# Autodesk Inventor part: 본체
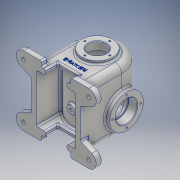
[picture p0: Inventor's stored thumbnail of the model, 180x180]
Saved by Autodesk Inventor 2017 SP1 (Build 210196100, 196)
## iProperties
Part Number: 본체
Material: 알루미늄 6061
Document SubType Name: Modeling
Designer: MRC
Density: 2.7 g/cm^3
Appearance: 알루미늄 - 평지
Mass: 1387.79 g
Surface Area: 1149.51 cm^2
Volume: 513.996 cm^3
Author: MRC
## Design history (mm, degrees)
sketch "스케치1"
  geometry: C1 r 45 at (0, 0); 1 further point
  constraints: 1 centre point, 1 coincident
  dimensions: "d0" = 90 diameter of C1
extrude "돌출1" new body sketch "스케치1" stored distance "d1" = 108; taper "d2" = 0 deg
sketch "스케치2"
  geometry: L1 (-45, 0)-(45, 0); L2 (45, 0)-(45, -76); L3 (45, -76)-(-45, -76); L4 (-45, -76)-(-45, 0); 2 further points
  constraints: 8 end point, 2 parallel, 1 horizontal, 1 horizontal alignment, 1 perpendicular, 1 vertical, 1 other
  dimensions: "d3" = 90 distance of L2.end L3.end; "d4" = 76 distance of L1.end L2.end
extrude "돌출2" join sketch "스케치2" stored distance "d5" = 108; taper "d6" = 0 deg
sketch "스케치3"
  geometry: L1 (0, -54)-(0, 54) reference; L2 (0, 54)-(0, -14); C1 r 31 at (0, -14); 1 further point
  constraints: 2 end point, 1 centre point, 1 coincident, 1 point on line
  dimensions: "d7" = 68 distance of L1.end L2.end; "d8" = 62 diameter of C1
extrude "돌출3" join sketch "스케치3" stored distance "d9" = 108; taper "d10" = 0 deg
node "작업 평면1"
sketch "스케치4"
  geometry: L1 (45, 54)-(-45, 54) reference; L2 (0, 54)-(0, -14); C1 r 7.5 at (0, -14); 1 further point
  constraints: 2 end point, 1 centre point, 1 coincident, 1 midpoint, 1 vertical
  dimensions: "d11" = 68 distance of L2.start L2.end; "d12" = 15 diameter of C1
extrude "돌출4" join sketch "스케치4" distance "d13" = 4; taper "d15" = 0 deg; dims "d14" = 4, "d16" = 0
sketch "스케치6"
  geometry: C1 r 17.5 at (0, 0); 1 further point
  constraints: 1 centre point
  dimensions: "d20" = 35 diameter of C1
extrude "돌출6" cut sketch "스케치6" stored distance "d21" = 6; taper "d22" = 0 deg
sketch "스케치7"
  geometry: C1 r 20 at (0, 0); 1 further point
  constraints: 1 centre point
  dimensions: "d23" = 40 diameter of C1
extrude "돌출7" cut sketch "스케치7" distance "d24" = 16; taper "d25" = 0 deg
sketch "스케치8"
  geometry: C1 r 20 at (0, 0); 1 further point
  constraints: 1 centre point
  dimensions: "d26" = 40 diameter of C1
extrude "돌출8" cut sketch "스케치8" distance "d27" = 16; taper "d28" = 0 deg
sketch "스케치9" dims "d29" = 52
  geometry: 6 further points
  constraints: 1 vertical alignment, 7 other
  dimensions: "d32" = 360 deg dimension on point (0, 0) point (0, 26) (derived)
hole "구멍1" sketch "스케치9" at (0, 26), (-26, 0), (0, -26), (26, 0) diameter "d34" = 3.242; stored, may be unused: countersink angle "d38" = 90 deg, drill point angle "d40" = 118 deg; dims "d35" = 8, "d36" = 4, "d37" = 2, "d39" = 10
sketch "스케치11"
  geometry: C1 r 28.5 at (0, 0); 1 further point
  constraints: 1 centre point, 1 coincident
  dimensions: "d44" = 57 diameter of C1
extrude "돌출10" join sketch "스케치11" distance "d45" = 6; taper "d46" = 0 deg
sketch "스케치12"
  geometry: C1 r 16.5 at (0, 0); 1 further point
  constraints: 1 centre point, 1 coincident
  dimensions: "d47" = 33 diameter of C1
extrude "돌출11" cut sketch "스케치12" distance "d48" = 15; taper "d49" = 0 deg
sketch "스케치13"
  geometry: C1 r 36 at (0, 0); 1 further point
  constraints: 1 centre point, 1 coincident
  dimensions: "d50" = 72 diameter of C1
extrude "돌출12" cut sketch "스케치13" distance "d51" = 90; taper "d52" = 0 deg
sketch "스케치14" dims "d53" = 46
  geometry: 6 further points
  constraints: 1 coincident, 1 vertical alignment, 7 other
  dimensions: "d56" = 360 deg dimension on point (0, 0) point (0, 23) (derived)
hole "구멍2" sketch "스케치14" at (0, 23), (-23, 0), (0, -23), (23, 0) diameter "d58" = 3.242; stored, may be unused: countersink angle "d62" = 90 deg, drill point angle "d64" = 118 deg; dims "d59" = 8, "d60" = 4, "d61" = 2, "d63" = 10
node "작업 평면2"
sketch "스케치15"
  geometry: L1 (-45, 0)-(-45, -76) reference; L2 (-45, 0)-(-45, -76); L3 (45, -76)-(-45, -76) reference; L4 (-45, -76)-(45, -76); L5 (45, 0)-(45, -76) reference; L6 (45, -76)-(45, 0); A1 r 45 centre (0, 0) between (-45, 0) and (45, 0); 1 further point
  constraints: 7 end point, 2 collinear, 2 point on circle, 1 centre point, 1 coincident, 1 horizontal
extrude "돌출13" cut sketch "스케치15" stored distance "d67" = 90; taper "d68" = 0 deg
node "작업 평면3"
sketch "스케치16"
  geometry: L1 (-45, -54)-(45, -54) reference; L2 (45, -54)-(45, 54) reference; L3 (-45, -54)-(45, -54); L4 (45, -54)-(45, 54); L5 (45, 54)-(-45, 54); L6 (-45, 54)-(-45, -54); L7 (-36, 45)-(36, 45); L8 (36, 45)-(36, -45); L9 (36, -45)-(-36, -45); L10 (-36, -45)-(-36, 45); 1 further point
  constraints: 16 end point, 4 parallel, 2 perpendicular, 1 horizontal, 1 point on line, 3 other
  dimensions: "d70" = 9 distance between parallel lines of L5 L7
extrude "돌출14" join sketch "스케치16" stored distance "d71" = 90; taper "d72" = 0 deg
sketch "스케치17"
  geometry: L1 (-20, 0)-(20, 0) reference; C1 r 20 at (0, 0); 1 further point
  constraints: 1 centre point, 1 midpoint
  dimensions: "d73" = 40 diameter of C1
extrude "돌출15" cut sketch "스케치17" stored distance "d74" = 90; taper "d75" = 0 deg
sketch "스케치18"
  geometry: C1 r 20 at (0, 0); 1 further point
  constraints: 1 centre point
  dimensions: "d76" = 40 diameter of C1
extrude "돌출16" cut sketch "스케치18" stored distance "d77" = 90; taper "d78" = 0 deg
sketch "스케치19"
  geometry: L1 (0, 0)-(0, -76.109); L2 (0, -76.109)-(20, -76.109); L3 (20, -76.109)-(20, -53.109); L4 (20, -53.109)-(-20, -53.109); L5 (-20, -53.109)-(-20, -76.109); L6 (-20, -76.109)-(0, -76.109)
  constraints: 12 end point, 2 perpendicular, 1 horizontal, 1 point on line, 1 vertical
  dimensions: "d79" = 20 distance of L1.end L2.end; "d80" = 23 distance of L2.end L3.end; "d81" = 40 distance of L3.end L4.end; "d82" = 23 distance of L4.end L5.end
extrude "돌출17" cut sketch "스케치19" stored distance "d83" = 90; taper "d84" = 0 deg
sketch "스케치20"
  geometry: L1 (-45, 54)-(-45, -54) reference; L2 (-45, -54)-(-20, -54) reference; L3 (-36, 45)-(-36, -45) reference; L4 (-36, -45)-(-20, -45) reference; L5 (-60, -64)-(-27, -64); L6 (-27, -64)-(-27, -45); L7 (-36, -23.994)-(-45, -28); L8 (-45, -28)-(-65.693, -37.21); A1 r 14 centre (-60, -50) between (-65.693, -37.21) and (-60, -64); 1 further point
  constraints: 8 end point, 3 point on line, 3 tangent, 2 point on circle, 1 centre point, 1 horizontal, 1 perpendicular
  dimensions: "d87" = 14 radius of A1; "d88" = 50 vertical distance of point (0, 0) A1.centre; "d89" = 60 horizontal distance of point (0, 0) A1.centre; "d90" = 18 distance between parallel lines of L1 L6; "d91" = 36 distance from line of L7.end L5
extrude "돌출18" join sketch "스케치20" distance "d92" = 12; taper "d93" = 0 deg
sketch "스케치21"
  geometry: 2 further points
hole "구멍3" sketch "스케치21" at (0, 0) diameter "d94" = 5.188; stored, may be unused: countersink angle "d98" = 90 deg, drill point angle "d100" = 118 deg; dims "d95" = 12, "d96" = 4, "d97" = 2, "d99" = 16
fillet "모깎기1" dims "d101" = 0.3
chamfer "모따기1" distance "d102" = 1; stored, may be unused: second distance "d103" = 2, angle "d104" = 45 deg
fillet "모깎기2" dims "d105" = 3
sketch "스케치22"
  geometry: A1 r 14 centre (120, -14) between (125.693, -26.79) and (120, 0) reference; 2 further points
  constraints: 1 coincident
hole "구멍4" sketch "스케치22" at (120, -14) diameter "d106" = 6.6; stored, may be unused: countersink angle "d110" = 90 deg, drill point angle "d112" = 118 deg; dims "d107" = 12, "d108" = 18, "d109" = 2, "d111" = 12
fillet "모깎기3" dims "d113" = 3
fillet "모깎기4" dims "d114" = 12
fillet "모깎기5" dims "d115" = 3
fillet "모깎기6" dims "d116" = 3
fillet "모깎기7" dims "d117" = 3
fillet "모깎기8" dims "d118" = 3
fillet "모깎기9" dims "d119" = 3
fillet "모깎기10" dims "d120" = 3
fillet "모깎기11" dims "d121" = 3
sketch "스케치23"
  geometry: L1 (60, -76)-(30, -76) reference; 2 further points
  constraints: 1 vertical alignment, 1 other
  dimensions: "d122" = 35 distance from line of L1 point (0, -41)
feature "엠보싱1" sketch "스케치23" dims "d123" = 0.5, "d124" = 0
node "솔리드1"
mirror "미러1"
mirror "미러2"
mirror "미러3"
mirror "미러4"
mirror "미러5"
mirror "미러6"
other parameters: "d65" = -76, "d69" = -76
